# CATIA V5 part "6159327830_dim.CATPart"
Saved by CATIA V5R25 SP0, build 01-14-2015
Part number: 6159327830_dim
Source: made
Property "PROI_CREATED_ON": "12/17/2008 9:21:37 AM"
Property "BLANK_DRAWING": "--"
Property "DRAWN_BY": "FPA"
Property "FINISH": "--"
Property "HEAT_TREATMENT": "ASSIGN"
Property "MATERIAL": "ASSIGN"
Property "PROJECT": "--"
Property "PROTOTYPE_NO": "--"
Property "RELATED_DRAWING": "--"
Property "COMPLETE_MATERIAL": "ASSIGN-ASSIGN"
Property "DESCRIPTION": "AXM-SX"
Property "DRAWING_EXIST": "--"
Property "MANUFACTURER": "--"
Property "MANUFACTURER_2": "--"
Property "MANUFACTURER_REF": "--"
Property "TYPE_PART": "--"
Property "TODAY_DATE": "2024/09/16"
Property "PDMREV": "01.0"
Property "PDMRL": "Production"
Property "PROI_REVISION": "01"
Property "PROI_VERSION": "0"
Property "PROI_RELEASE": "Production"
Property "PTC_MODIFIED": false
Property "MFG_WP_MATERIAL": "ASSIGN"
Property "COMPANY_CODE": "---"
Property "DESCRIPTION_JP": "--"
Property "PQP_DOCUMENT": "--"
Property "GHOST": false
Property "NO_PART": false
Property "REFERENCE": "6159327830_DIM"
Property "PTC_WM_ITERATION": "0"
Property "PTC_WM_VERSION": "01.0"
Property "PTC_WM_CREATED_ON": "16-Sep-24 10:44:40 AM"
Property "PTC_WM_MODIFIED_ON": "16-Sep-24 10:45:59 AM"
Property "PTC_WM_NAME": "6159327830_dim.prt"
Property "PTC_WM_NUMBER": "6159327830_DIM.PRT"
Property "PTC_WM_LIFECYCLE_STATE": "Production"
Property "PTC_WM_LIFECYCLE": "Design_Process"
Property "PTC_WM_REVISION": "01"
Property "PTC_WM_CREATED_BY": "Florian Pavageau (Grefpav) (Grefpav: CPD)"
Property "PTC_WM_MODIFIED_BY": "Florian Pavageau (Grefpav) (Grefpav: CPD)"
Property "PTC_ORGANIZATION_ID": "CPD"
Property "PTC_WM_LOCATION": "/Products/CONTROLLERS/A1770 - CX4 - SMART DRIVE - LEAN/9-01-Dimensional Drawings"
Property "PTC_WM_PART_NAME": "6159327830_dim.prt"
Property "PTC_WM_PART_NUMBER": "6159327830_DIM"
Property "PTC_WM_TEAM": "Default"
Property "PTC_COMMON_NAME": "6159327830_dim.prt"
Property "PTC_MASTER_MATERIAL": "ASSIGN"
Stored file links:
  d:\ptc\Echange\temp\6159327830_dim.CATPart

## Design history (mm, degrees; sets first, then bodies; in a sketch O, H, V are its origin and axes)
AxisSystem1 "CS0": origin (0, 0, 0), X (1, 0, 0), Y (0, 1, 0), Z (0, 0, 1)
Set1
  DatumSurface1 "Sheet.1"
  DatumSurface2 "Sheet.2"
  DatumSurface3 "Sheet.3"
  DatumSurface4 "Sheet.4"
  DatumSurface5 "Sheet.5"
  DatumSurface6 "Sheet.6"
  DatumSurface7 "Sheet.7"
  DatumSurface8 "Sheet.8"
  DatumSurface9 "Sheet.9"
  DatumSurface10 "Sheet.10"
  DatumSurface11 "Sheet.11"
  DatumSurface12 "Sheet.12"
  DatumSurface13 "Sheet.13"
  DatumSurface14 "Sheet.14"
  DatumSurface15 "Sheet.15"
  DatumSurface16 "Sheet.16"
  DatumSurface17 "Sheet.17"
  Plane1 "RIGHT": stored without definition
  Plane2 "TOP": stored without definition
  Plane3 "FRONT": stored without definition
Body1 "PartBody" (main body)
